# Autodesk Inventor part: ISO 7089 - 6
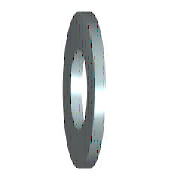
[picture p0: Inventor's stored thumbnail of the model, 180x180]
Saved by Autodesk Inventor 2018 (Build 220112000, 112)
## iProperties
Created: 2017-02
Part Number: ISO 7089 - 6
Material: Acier inoxydable
Description: Rondelles plates - Série standard - Produit de classe A
Document SubType Name: Modeling
Standard: ISO 7089
Designer: TJ
Standard Revision: Second edition 2000-06-01
Standards Organization: ISO
Language: fr-FR
Size Designation: 6
Categories: <MemberInstance><Categories><Category DisplayName="Visserie" InternalName="e4da775c-781d-43d5-af7c-5136215cf5a6" Mnemonic="FSTN"><Category DisplayName="Rondelle
Density: 8 g/cm^3
Appearance: Semi-poli
IsCustomPart: 0
Author: TJ
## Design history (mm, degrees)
sketch "Esquisse"
  geometry: C1 r 6 at (0, 0); C2 r 3.2 at (0, 0); 1 further point
  constraints: 2 centre point, 2 coincident
  dimensions: "d0" = 6.4 diameter of C2 (= SD1); "d1" = 12 diameter of C1 (= SD2)
extrude "Corps" new body sketch "Esquisse" distance "d2" = 1.6 (= SD); taper "d3" = 0 deg
workaxis "Work Axis1"
workplane "Work Plane1"
body "Solid1"
other parameters: "SD1" = 6.4 [user parameter; used in 1 equation term], "SD2" = 12 [user parameter; used in 1 equation term], "SD" = 1.6 [user parameter; used in 1 equation term], "d4" = 0, "d5" = 0, "d6" = 0, "d7" = 0, "NND" = 6 [user parameter]
